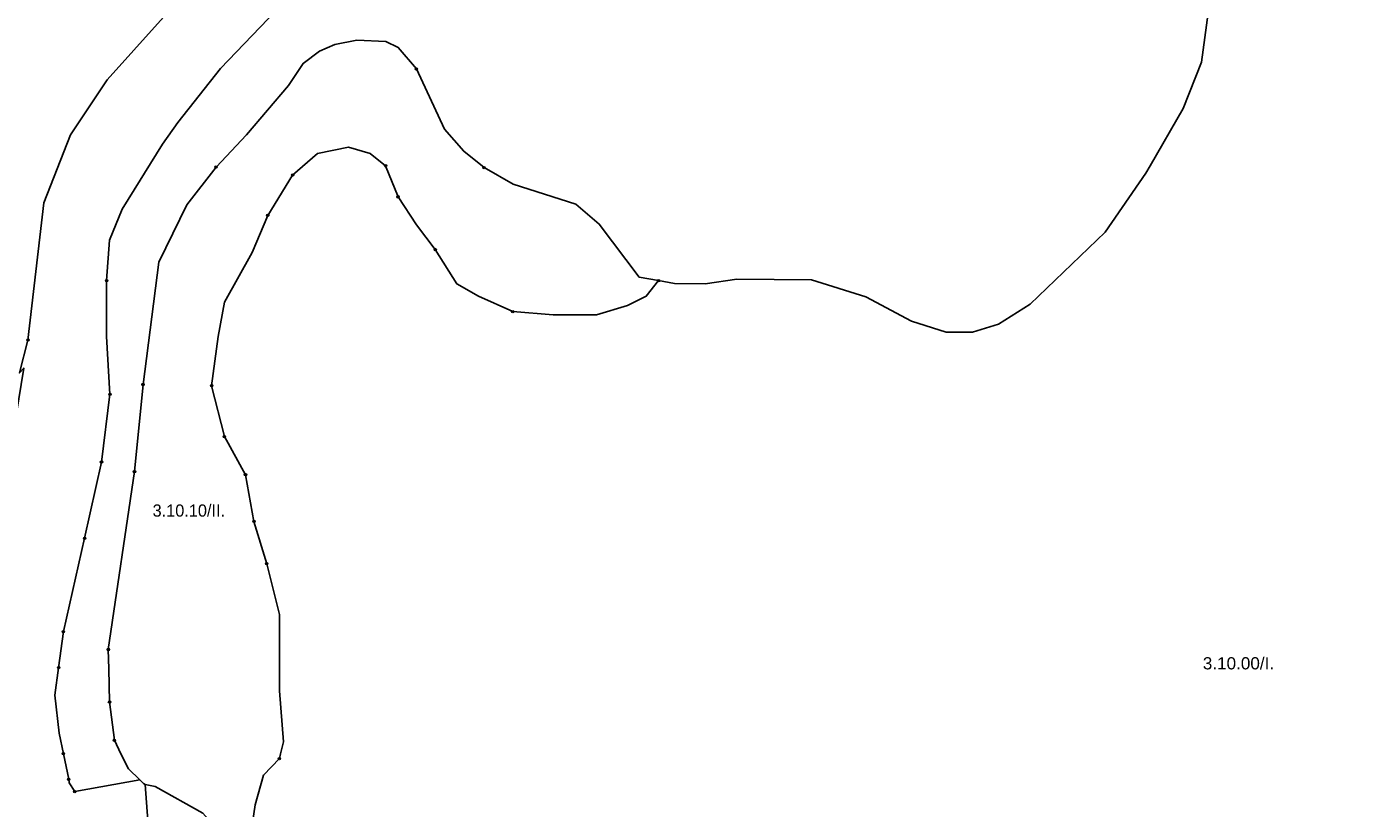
# Model space of a CAD drawing. Extents: x -650455 to -642254, y -1075222 to -1066610.
# Drawn here: x -645923 to -644838, y -1070045 to -1069403 of the extents above; entities that cross this region are included whole.
import ezdxf
from ezdxf.enums import TextEntityAlignment as Align

# ---------------------------------------------------------------- set-up
doc = ezdxf.new("R2010")
doc.units = 0
doc.header["$LTSCALE"] = 4
doc.header["$PDMODE"] = 32
doc.header["$PDSIZE"] = 2
for name, color, linetype, lineweight in [('1', 7, 'Continuous', 25), ('11', 7, 'Continuous', 13), ('12', 7, 'Continuous', 13), ('13', 7, 'Continuous', 13), ('14', 7, 'Continuous', 13), ('15', 7, 'Continuous', 13)]:
    doc.layers.add(name, color=color, linetype=linetype, lineweight=lineweight)
doc.layers.add('2', color=7, linetype='Continuous')

msp = doc.modelspace()

# ---------------------------------------------------------------- linework, layer by layer
at = {"layer": '1'}
for points in [[(-645960, -1069928), (-645957.5, -1069916.501), (-645945.5, -1069826), (-645941.5, -1069786), (-645925, -1069683.5), (-645928.5, -1069687.5), (-645921.5, -1069660.5), (-645908.5, -1069548.001), (-645886.5, -1069492.001), (-645856.5, -1069447.001), (-645698.133, -1069270.881), (-645694.109, -1069269.277), (-645694.125, -1069269.251), (-645637, -1069246.5), (-645633.75, -1069245.251), (-645633.394, -1069245.058), (-645602, -1069232.501), (-645598.374, -1069232.751)], [(-645698.133, -1069270.881), (-645856.5, -1069447.001), (-645886.5, -1069492.001)], [(-645767, -1069518.5), (-645791, -1069549.5), (-645814, -1069596.501), (-645827, -1069697), (-645834, -1069768.5), (-645855.5, -1069914.5), (-645855.128, -1069930.498), (-645854.5, -1069957.501), (-645850.5, -1069989.001), (-645845.117, -1070000), (-645839, -1070012.5), (-645829.689, -1070021.439), (-645883.117, -1070031.08), (-645887.546, -1070024.046), (-645888.048, -1070021.037), (-645892.4, -1070000), (-645895.872, -1069983.218), (-645899.35, -1069951.919), (-645896.363, -1069929.516), (-645892.395, -1069899.754), (-645875.006, -1069823.246), (-645861.096, -1069760.648), (-645854.14, -1069705.005), (-645856.947, -1069657.538), (-645856.947, -1069611.709), (-645854.401, -1069578.61), (-645844.217, -1069553.15), (-645811.118, -1069499.682), (-645798.388, -1069481.86), (-645763.379, -1069437.622), (-645704.82, -1069376.516)], [(-645704.82, -1069376.516), (-645763.379, -1069437.622), (-645798.388, -1069481.86), (-645811.118, -1069499.682), (-645844.217, -1069553.15), (-645854.401, -1069578.61), (-645856.947, -1069611.709), (-645856.947, -1069657.538), (-645854.14, -1069705.005), (-645861.096, -1069760.648), (-645875.006, -1069823.246), (-645892.395, -1069899.754), (-645896.363, -1069929.516), (-645899.35, -1069951.919), (-645895.872, -1069983.218), (-645892.4, -1070000), (-645888.048, -1070021.037), (-645887.546, -1070024.046), (-645883.117, -1070031.08), (-645829.689, -1070021.439), (-645826.5, -1070024.5), (-645825.17, -1070025.403), (-645821.972, -1070069.724)], [(-644952.5, -1069392), (-644958, -1069432.5), (-644973, -1069470.5), (-645000, -1069517.419), (-645003.5, -1069523.501), (-645037, -1069572.001), (-645098.5, -1069631), (-645124.5, -1069647.5), (-645146, -1069654.001), (-645167.5, -1069654.001), (-645196, -1069645.001), (-645233.5, -1069625.001), (-645278, -1069611), (-645339.5, -1069610.5), (-645365.5, -1069614.5), (-645390.5, -1069614.001), (-645403.753, -1069611.715), (-645419.5, -1069609.001), (-645452.5, -1069565.501), (-645471.5, -1069549.001), (-645523, -1069532.501), (-645547, -1069519), (-645563.5, -1069505.5), (-645579.5, -1069487.501), (-645602.5, -1069438), (-645617.5, -1069420.5), (-645627.5, -1069415.501), (-645651.5, -1069414.501), (-645669.5, -1069418.001), (-645682, -1069423.501), (-645695.5, -1069433.5), (-645707.5, -1069451.501), (-645742, -1069492.001), (-645767, -1069518.5)], [(-645602.341, -1069565.88), (-645587.065, -1069586.248), (-645569.242, -1069614.255), (-645551.42, -1069624.439), (-645523.413, -1069637.17), (-645490.314, -1069639.716), (-645454.67, -1069639.716), (-645429.209, -1069632.077), (-645413.932, -1069624.439), (-645403.753, -1069611.715), (-645390.5, -1069614.001), (-645365.5, -1069614.5), (-645339.5, -1069610.5), (-645278, -1069611), (-645233.5, -1069625.001), (-645196, -1069645.001), (-645167.5, -1069654.001), (-645146, -1069654.001), (-645124.5, -1069647.5), (-645098.5, -1069631), (-645037, -1069572.001), (-645003.5, -1069523.501), (-645000, -1069517.419), (-644973, -1069470.5), (-644958, -1069432.5), (-644952.5, -1069392)], [(-645839, -1070012.5), (-645845.117, -1070000), (-645850.5, -1069989.001), (-645854.5, -1069957.501), (-645855.128, -1069930.498), (-645855.5, -1069914.5), (-645834, -1069768.5), (-645827, -1069697), (-645814, -1069596.501), (-645791, -1069549.5), (-645767, -1069518.5), (-645742, -1069492.001), (-645707.5, -1069451.501), (-645695.5, -1069433.5), (-645682, -1069423.501), (-645669.5, -1069418.001), (-645651.5, -1069414.501), (-645627.5, -1069415.501), (-645617.5, -1069420.5), (-645602.5, -1069438), (-645579.5, -1069487.501), (-645563.5, -1069505.5), (-645547, -1069519), (-645523, -1069532.501), (-645471.5, -1069549.001), (-645452.5, -1069565.501), (-645419.5, -1069609.001), (-645403.753, -1069611.715)], [(-645886.5, -1069492.001), (-645908.5, -1069548.001), (-645921.5, -1069660.5), (-645928.5, -1069687.5)], [(-645403.753, -1069611.715), (-645413.932, -1069624.439), (-645429.209, -1069632.077), (-645454.67, -1069639.716), (-645490.314, -1069639.716), (-645523.413, -1069637.17), (-645551.42, -1069624.439), (-645569.242, -1069614.255), (-645587.065, -1069586.248), (-645602.341, -1069565.88), (-645617.617, -1069542.965), (-645627.802, -1069517.505), (-645640.532, -1069507.32), (-645658.354, -1069502.228), (-645683.815, -1069507.32), (-645704.184, -1069525.143), (-645724.552, -1069558.242), (-645737.282, -1069588.794), (-645760.197, -1069629.531), (-645765.289, -1069657.538), (-645770.677, -1069698.05), (-645760.244, -1069739.782), (-645742.855, -1069771.081), (-645735.9, -1069809.335), (-645725.467, -1069844.112), (-645715.034, -1069885.843), (-645715.034, -1069948.441), (-645711.556, -1069990.173), (-645714.013, -1070000), (-645715.034, -1070004.084), (-645728.075, -1070017.56), (-645735.031, -1070041.903), (-645741.915, -1070090.098)], [(-645741.915, -1070090.098), (-645735.031, -1070041.903), (-645728.075, -1070017.56), (-645715.034, -1070004.084), (-645714.013, -1070000), (-645711.556, -1069990.173), (-645715.034, -1069948.441), (-645715.034, -1069885.843), (-645725.467, -1069844.112), (-645735.9, -1069809.335), (-645742.855, -1069771.081), (-645760.244, -1069739.782), (-645770.677, -1069698.05), (-645765.289, -1069657.538), (-645760.197, -1069629.531), (-645737.282, -1069588.794), (-645724.552, -1069558.242), (-645704.184, -1069525.143), (-645683.815, -1069507.32), (-645658.354, -1069502.228), (-645640.532, -1069507.32), (-645627.802, -1069517.505), (-645617.617, -1069542.965), (-645602.341, -1069565.88)], [(-645777.762, -1070048.899), (-645817.043, -1070027.048), (-645825.17, -1070025.403), (-645826.5, -1070024.5), (-645829.689, -1070021.439), (-645839, -1070012.5)], [(-645821.972, -1070069.724), (-645825.17, -1070025.403), (-645817.043, -1070027.048), (-645777.762, -1070048.899)]]:
    msp.add_lwpolyline(points, dxfattribs=at)
at = {"layer": '11'}
for p, q in [((-645742.855, -1069771.081), (-645735.9, -1069809.335)), ((-645735.9, -1069809.335), (-645725.467, -1069844.112))]:
    msp.add_line(p, q, dxfattribs=at)
for points in [[(-645941.5, -1069786), (-645925, -1069683.5), (-645928.5, -1069687.5), (-645921.5, -1069660.5), (-645908.5, -1069548.001), (-645886.5, -1069492.001), (-645856.5, -1069447.001), (-645698.133, -1069270.881), (-645695.195, -1069267.614), (-645695.188, -1069267.626), (-645687, -1069258.5), (-645636.5, -1069209.001), (-645431, -1069051.5), (-645370.25, -1069009.125)], [(-644836.38, -1069033.691), (-644871, -1069046.001), (-644887.558, -1069053.097), (-644888.516, -1069053.508), (-644917.772, -1069066.77), (-644932.672, -1069073.465), (-644937.5, -1069079.501), (-644948.5, -1069112.5), (-644954, -1069141), (-644954.5, -1069168.001), (-644950.5, -1069283.5), (-644952.5, -1069392), (-644958, -1069432.5), (-644973, -1069470.5), (-645000, -1069517.419), (-645003.5, -1069523.501), (-645037, -1069572.001), (-645098.5, -1069631), (-645124.5, -1069647.5), (-645146, -1069654.001), (-645167.5, -1069654.001)], [(-645627.802, -1069517.505), (-645640.532, -1069507.32), (-645658.354, -1069502.228), (-645683.815, -1069507.32), (-645704.184, -1069525.143), (-645724.552, -1069558.242)], [(-645587.065, -1069586.248), (-645602.341, -1069565.88), (-645617.617, -1069542.965), (-645627.802, -1069517.505)], [(-645724.552, -1069558.242), (-645737.282, -1069588.794), (-645760.197, -1069629.531), (-645765.289, -1069657.538), (-645770.677, -1069698.05), (-645760.244, -1069739.782), (-645742.855, -1069771.081)], [(-645403.753, -1069611.715), (-645413.932, -1069624.439), (-645429.209, -1069632.077), (-645454.67, -1069639.716), (-645490.314, -1069639.716), (-645523.413, -1069637.17), (-645551.42, -1069624.439), (-645569.242, -1069614.255), (-645587.065, -1069586.248)], [(-645167.5, -1069654.001), (-645196, -1069645.001), (-645233.5, -1069625.001), (-645278, -1069611), (-645339.5, -1069610.5), (-645365.5, -1069614.5), (-645390.5, -1069614.001), (-645403.753, -1069611.715)], [(-645725.467, -1069844.112), (-645715.034, -1069885.843), (-645715.034, -1069948.441), (-645711.556, -1069990.173), (-645714.013, -1070000), (-645715.034, -1070004.084), (-645728.075, -1070017.56), (-645735.031, -1070041.903), (-645741.915, -1070090.098), (-645726.5, -1070110.501), (-645703.5, -1070164.501), (-645696, -1070191.501), (-645694.628, -1070206.315), (-645696.21, -1070230.279), (-645696.21, -1070233.478), (-645696.21, -1070244.446), (-645693.219, -1070253.691)]]:
    msp.add_lwpolyline(points, dxfattribs=at)
for p in [(-645627.802, -1069517.505), (-645724.552, -1069558.242), (-645587.065, -1069586.248), (-645403.753, -1069611.715), (-645742.855, -1069771.081), (-645735.9, -1069809.335), (-645725.467, -1069844.112)]:
    msp.add_point(p, dxfattribs=at)
at = {"layer": '12'}
for p, q in [((-645724.552, -1069558.242), (-645704.184, -1069525.143)), ((-645760.244, -1069739.782), (-645770.677, -1069698.05)), ((-645854.5, -1069957.501), (-645850.5, -1069989.001))]:
    msp.add_line(p, q, dxfattribs=at)
for points in [[(-645602.5, -1069438), (-645617.5, -1069420.5), (-645627.5, -1069415.501), (-645651.5, -1069414.501), (-645669.5, -1069418.001), (-645682, -1069423.501), (-645695.5, -1069433.5), (-645707.5, -1069451.501), (-645742, -1069492.001), (-645767, -1069518.5)], [(-645547, -1069519), (-645563.5, -1069505.5), (-645579.5, -1069487.501), (-645602.5, -1069438)], [(-645704.184, -1069525.143), (-645683.815, -1069507.32), (-645658.354, -1069502.228), (-645640.532, -1069507.32), (-645627.802, -1069517.505), (-645617.617, -1069542.965)], [(-645767, -1069518.5), (-645791, -1069549.5), (-645814, -1069596.501), (-645827, -1069697), (-645834, -1069768.5), (-645855.5, -1069914.5)], [(-645523.413, -1069637.17), (-645490.314, -1069639.716), (-645454.67, -1069639.716), (-645429.209, -1069632.077), (-645413.932, -1069624.439), (-645403.753, -1069611.715), (-645419.5, -1069609.001), (-645452.5, -1069565.501), (-645471.5, -1069549.001), (-645523, -1069532.501), (-645547, -1069519)], [(-645617.617, -1069542.965), (-645602.341, -1069565.88), (-645587.065, -1069586.248), (-645569.242, -1069614.255), (-645551.42, -1069624.439), (-645523.413, -1069637.17)], [(-645770.677, -1069698.05), (-645765.289, -1069657.538), (-645760.197, -1069629.531), (-645737.282, -1069588.794), (-645724.552, -1069558.242)], [(-645735.9, -1069809.335), (-645742.855, -1069771.081), (-645760.244, -1069739.782)], [(-645715.034, -1070004.084), (-645714.013, -1070000), (-645711.556, -1069990.173), (-645715.034, -1069948.441), (-645715.034, -1069885.843), (-645725.467, -1069844.112), (-645735.9, -1069809.335)], [(-645855.5, -1069914.5), (-645855.128, -1069930.498), (-645854.5, -1069957.501)], [(-645850.5, -1069989.001), (-645845.117, -1070000), (-645839, -1070012.5), (-645829.689, -1070021.439), (-645826.5, -1070024.5), (-645825.17, -1070025.403), (-645817.043, -1070027.048), (-645777.762, -1070048.899), (-645757.472, -1070072.051), (-645741.915, -1070090.098), (-645735.031, -1070041.903), (-645728.075, -1070017.56), (-645715.034, -1070004.084)]]:
    msp.add_lwpolyline(points, dxfattribs=at)
for p in [(-645602.5, -1069438), (-645767, -1069518.5), (-645704.184, -1069525.143), (-645547, -1069519), (-645617.617, -1069542.965), (-645724.552, -1069558.242), (-645523.413, -1069637.17), (-645770.677, -1069698.05), (-645760.244, -1069739.782), (-645735.9, -1069809.335), (-645855.5, -1069914.5), (-645854.5, -1069957.501), (-645850.5, -1069989.001), (-645715.034, -1070004.084)]:
    msp.add_point(p, dxfattribs=at)
at = {"layer": '13'}
msp.add_lwpolyline([(-645777.762, -1070048.899), (-645817.043, -1070027.048), (-645825.17, -1070025.403), (-645821.972, -1070069.724)], dxfattribs=at)
at = {"layer": '14'}
for p, q in [((-645834, -1069768.5), (-645827, -1069697)), ((-645861.096, -1069760.648), (-645875.006, -1069823.246)), ((-645892.4, -1070000), (-645888.048, -1070021.037))]:
    msp.add_line(p, q, dxfattribs=at)
for points in [[(-645704.82, -1069376.516), (-645763.379, -1069437.622), (-645798.388, -1069481.86), (-645811.118, -1069499.682), (-645844.217, -1069553.15), (-645854.401, -1069578.61), (-645856.947, -1069611.709)], [(-645471.5, -1069549.001), (-645452.5, -1069565.501), (-645419.5, -1069609.001), (-645403.753, -1069611.715), (-645390.5, -1069614.001), (-645365.5, -1069614.5), (-645339.5, -1069610.5), (-645278, -1069611), (-645233.5, -1069625.001), (-645196, -1069645.001), (-645167.5, -1069654.001), (-645146, -1069654.001), (-645124.5, -1069647.5), (-645098.5, -1069631), (-645037, -1069572.001), (-645003.5, -1069523.501), (-645000, -1069517.419), (-644973, -1069470.5), (-644958, -1069432.5), (-644952.5, -1069392)], [(-645827, -1069697), (-645814, -1069596.501), (-645791, -1069549.5), (-645767, -1069518.5), (-645742, -1069492.001), (-645707.5, -1069451.501), (-645695.5, -1069433.5), (-645682, -1069423.501), (-645669.5, -1069418.001), (-645651.5, -1069414.501), (-645627.5, -1069415.501), (-645617.5, -1069420.5), (-645602.5, -1069438), (-645579.5, -1069487.501), (-645563.5, -1069505.5), (-645547, -1069519), (-645523, -1069532.501), (-645471.5, -1069549.001)], [(-645856.947, -1069611.709), (-645856.947, -1069657.538), (-645854.14, -1069705.005), (-645861.096, -1069760.648)], [(-645888.048, -1070021.037), (-645887.546, -1070024.046), (-645883.117, -1070031.08), (-645829.689, -1070021.439), (-645839, -1070012.5), (-645845.117, -1070000), (-645850.5, -1069989.001), (-645854.5, -1069957.501), (-645855.128, -1069930.498), (-645855.5, -1069914.5), (-645834, -1069768.5)], [(-645875.006, -1069823.246), (-645892.395, -1069899.754), (-645896.363, -1069929.516)], [(-645896.363, -1069929.516), (-645899.35, -1069951.919), (-645895.872, -1069983.218), (-645892.4, -1070000)]]:
    msp.add_lwpolyline(points, dxfattribs=at)
for p in [(-645856.947, -1069611.709), (-645827, -1069697), (-645861.096, -1069760.648), (-645834, -1069768.5), (-645875.006, -1069823.246), (-645896.363, -1069929.516), (-645892.4, -1070000), (-645888.048, -1070021.037)]:
    msp.add_point(p, dxfattribs=at)
at = {"layer": '15'}
msp.add_line((-645892.395, -1069899.754), (-645875.006, -1069823.246), dxfattribs=at)
for points in [[(-645854.14, -1069705.005), (-645856.947, -1069657.538), (-645856.947, -1069611.709), (-645854.401, -1069578.61), (-645844.217, -1069553.15), (-645811.118, -1069499.682), (-645798.388, -1069481.86), (-645763.379, -1069437.622), (-645704.82, -1069376.516), (-645669.175, -1069333.233), (-645636.076, -1069289.95), (-645621.437, -1069268.627), (-645598.374, -1069232.751), (-645602, -1069232.501), (-645633.394, -1069245.058), (-645633.75, -1069245.251), (-645637, -1069246.5), (-645694.125, -1069269.251), (-645694.109, -1069269.277), (-645698.133, -1069270.881)], [(-645698.133, -1069270.881), (-645856.5, -1069447.001), (-645886.5, -1069492.001), (-645908.5, -1069548.001), (-645921.5, -1069660.5)], [(-645921.5, -1069660.5), (-645928.5, -1069687.5), (-645925, -1069683.5)], [(-645875.006, -1069823.246), (-645861.096, -1069760.648), (-645854.14, -1069705.005)], [(-645883.117, -1070031.08), (-645887.546, -1070024.046), (-645888.048, -1070021.037), (-645892.4, -1070000), (-645895.872, -1069983.218), (-645899.35, -1069951.919), (-645896.363, -1069929.516), (-645892.395, -1069899.754)], [(-645821.972, -1070069.724), (-645825.17, -1070025.403), (-645826.5, -1070024.5), (-645829.689, -1070021.439), (-645883.117, -1070031.08)]]:
    msp.add_lwpolyline(points, dxfattribs=at)
for p in [(-645921.5, -1069660.5), (-645854.14, -1069705.005), (-645875.006, -1069823.246), (-645892.395, -1069899.754), (-645883.117, -1070031.08)]:
    msp.add_point(p, dxfattribs=at)

# ---------------------------------------------------------------- texts
at = {"layer": '2'}
msp.add_text('3.10.10/II.', height=10, dxfattribs=at).set_placement((-645789.395, -1069805.446), align=Align.CENTER)
at = {"layer": '2', "width": 1.05}
msp.add_text('3.10.00/I.', height=10, dxfattribs=at).set_placement((-644927.532, -1069930.815), align=Align.CENTER)

doc.saveas('drawing.dxf')
